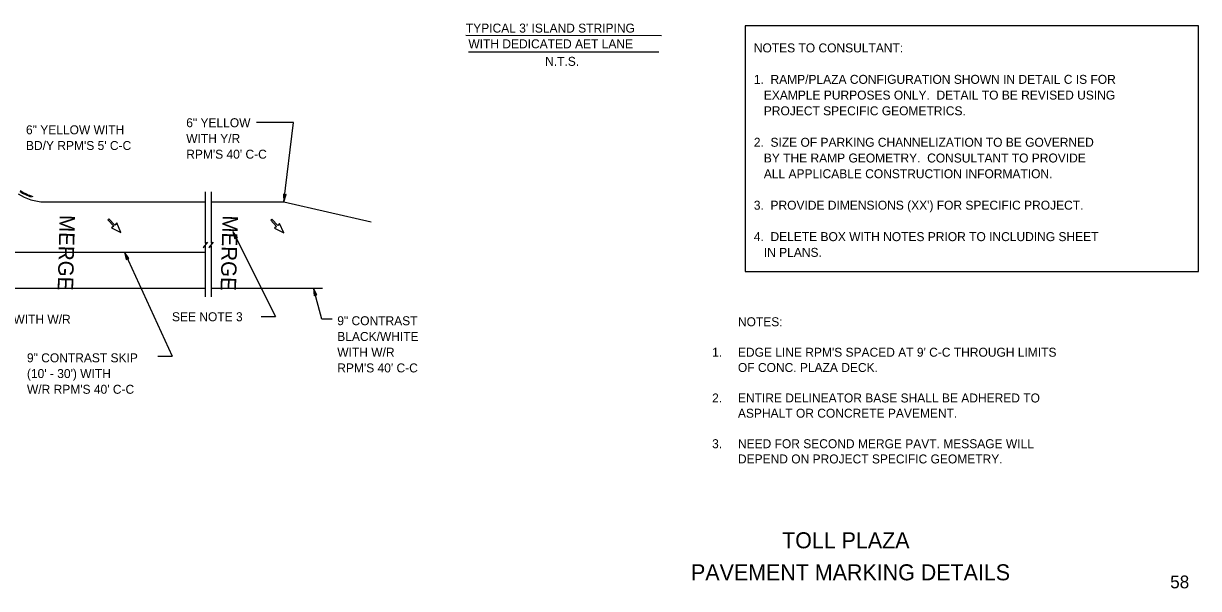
# Model space of a CAD drawing. Extents: x 583689 to 590775, y 1496016 to 1497365.
# Drawn here: x 587898 to 588815, y 1496041 to 1496482 of the extents above; entities that cross this region are included whole.
import ezdxf

# ---------------------------------------------------------------- set-up
doc = ezdxf.new("R2010")
doc.units = 0
for name, color, linetype in [('2', 7, 'Continuous'), ('20', 7, 'Continuous'), ('21', 7, 'Continuous'), ('24', 7, 'Continuous'), ('52', 7, 'Continuous'), ('6', 7, 'Continuous'), ('TextAlert', 7, 'Continuous'), ('TextMisc', 7, 'Continuous'), ('TextNotes', 7, 'Continuous'), ('TextShtNo', 7, 'Continuous')]:
    doc.layers.add(name, color=color, linetype=linetype)

msp = doc.modelspace()

# ---------------------------------------------------------------- linework, layer by layer
at = {"layer": '2'}
for p, q in [((587914.46, 1496343.13), (588039.9, 1496343.13)), ((588044.46, 1496343.13), (588101.26, 1496343.13)), ((588101.26, 1496343.13), (588169.33, 1496327.49)), ((587813.57, 1496303.79), (588039.9, 1496303.8)), ((587663.57, 1496275.75), (588039.9, 1496275.75)), ((588044.46, 1496275.75), (588131.47, 1496275.75))]:
    msp.add_line(p, q, dxfattribs=at)
for radius, end in [(37.5, 269.72056), (35.25, 253.06808), (34.5, 254.55783)]:
    msp.add_arc((587914.65, 1496380.63), radius, 236.43568, end, dxfattribs=at)
at = {"layer": '20'}
for p, q in [((587964.79, 1496329.9), (587963.89, 1496329.04)), ((587969.44, 1496325), (587964.79, 1496329.9)), ((587963.89, 1496329.04), (587968.53, 1496324.14)), ((587968.53, 1496324.14), (587966.84, 1496322.84)), ((587966.84, 1496322.84), (587974.15, 1496319.13)), ((587970.83, 1496326.63), (587969.44, 1496325)), ((587974.15, 1496319.13), (587970.83, 1496326.63)), ((588091.9, 1496329.59), (588091, 1496328.73)), ((588091, 1496328.73), (588095.64, 1496323.84)), ((588096.55, 1496324.7), (588091.9, 1496329.59)), ((588095.64, 1496323.84), (588093.95, 1496322.54)), ((588093.95, 1496322.54), (588101.26, 1496318.83)), ((588097.94, 1496326.33), (588096.55, 1496324.7)), ((588101.26, 1496318.83), (588097.94, 1496326.33))]:
    msp.add_line(p, q, dxfattribs=at)
at = {"layer": '21'}
for p, q in [((588243.28, 1496473.09), (588395.82, 1496473.08)), ((588245.24, 1496460.12), (588393.86, 1496460.11)), ((588108.87, 1496405.11), (588080.02, 1496405.16)), ((588101.26, 1496343.13), (588108.87, 1496405.11)), ((588039.9, 1496350.84), (588039.9, 1496310.79)), ((588044.46, 1496350.84), (588044.46, 1496310.79)), ((588041.64, 1496311.58), (588038.17, 1496307.48)), ((588039.9, 1496310.79), (588041.64, 1496311.58)), ((588046.19, 1496311.58), (588042.73, 1496307.48)), ((588044.46, 1496310.79), (588046.19, 1496311.58)), ((588061.46, 1496319.93), (588094.84, 1496253.66)), ((587976.89, 1496303.8), (588014.09, 1496222.75)), ((588038.17, 1496307.48), (588039.9, 1496308.74)), ((588039.9, 1496308.74), (588039.9, 1496269.01)), ((588042.73, 1496307.48), (588044.46, 1496308.74)), ((588044.46, 1496308.74), (588044.46, 1496269.01)), ((588130.93, 1496251.6), (588124.36, 1496275.75)), ((588083.63, 1496253.66), (588094.84, 1496253.66)), ((588138.85, 1496251.58), (588130.93, 1496251.6)), ((588002.88, 1496222.75), (588014.09, 1496222.75))]:
    msp.add_line(p, q, dxfattribs=at)
at = {"layer": '52'}
for p, q in [((588101.92, 1496348.45), (588100.9, 1496349.02)), ((588100.9, 1496349.02), (588101.26, 1496343.13)), ((588101.26, 1496343.13), (588103.08, 1496348.75)), ((588103.08, 1496348.75), (588101.92, 1496348.45)), ((588061.46, 1496319.93), (588063.07, 1496314.25)), ((588065.04, 1496315.24), (588061.46, 1496319.93)), ((588063.07, 1496314.25), (588063.88, 1496315.14)), ((588063.88, 1496315.14), (588065.04, 1496315.24)), ((587976.89, 1496303.8), (587978.29, 1496298.06)), ((587980.29, 1496298.97), (587976.89, 1496303.8)), ((587978.29, 1496298.06), (587979.13, 1496298.92)), ((587979.13, 1496298.92), (587980.29, 1496298.97)), ((588124.36, 1496275.75), (588124.8, 1496269.86)), ((588126.93, 1496270.44), (588124.36, 1496275.75)), ((588124.8, 1496269.86), (588125.77, 1496270.58)), ((588125.77, 1496270.58), (588126.93, 1496270.44))]:
    msp.add_line(p, q, dxfattribs=at)
at = {"layer": 'TextAlert'}
msp.add_lwpolyline([(588461.06, 1496288.7), (588814.9, 1496288.7), (588814.9, 1496480.56), (588461.06, 1496480.56)], close=True, dxfattribs=at)

# ---------------------------------------------------------------- texts
at = {"layer": '21'}
for s, p in [('6" YELLOW', (588025.07, 1496401.36)), ('6" YELLOW WITH', (587900.05, 1496395.85)), ('WITH Y/R', (588025.07, 1496389.08)), ("BD/Y RPM'S 5' C-C", (587900.05, 1496383.58)), ("RPM'S 40' C-C", (588025.07, 1496376.8)), ('SEE NOTE 3', (588013.96, 1496249.92)), ('9" CONTRAST BLACK/WHITE WITH W/R', (587758.97, 1496247.96)), ('9" CONTRAST', (588142.92, 1496246.8)), ('BLACK/WHITE', (588142.92, 1496234.52)), ('WITH W/R', (588142.92, 1496222.24)), ('9" CONTRAST SKIP', (587900.8, 1496217.86)), ("(10' - 30') WITH", (587900.8, 1496205.58)), ("RPM'S 40' C-C", (588142.92, 1496209.97)), ("W/R RPM'S 40' C-C", (587900.8, 1496193.3))]:
    msp.add_text(s, height=7, dxfattribs=at).set_placement(p)
at = {"layer": '24'}
for p in [(587926.36, 1496332.98), (588053.47, 1496332.67)]:
    msp.add_text('MERGE', height=11.999, rotation=268.44195, dxfattribs=at).set_placement(p)
at = {"layer": '6'}
for s, p in [("TYPICAL 3' ISLAND STRIPING", (588243.28, 1496475.23)), ('WITH DEDICATED AET LANE', (588245.24, 1496462.95)), ('N.T.S.', (588305.11, 1496449.28))]:
    msp.add_text(s, height=7, rotation=359.99873, dxfattribs=at).set_placement(p)
at = {"layer": 'TextAlert'}
for s, p in [('NOTES TO CONSULTANT:  ', (588467.95, 1496459.77)), ('1.  RAMP/PLAZA CONFIGURATION SHOWN IN DETAIL C IS FOR', (588467.95, 1496435.22)), ('   EXAMPLE PURPOSES ONLY.  DETAIL TO BE REVISED USING', (588467.95, 1496422.94)), ('   PROJECT SPECIFIC GEOMETRICS.', (588467.95, 1496410.66)), ('2.  SIZE OF PARKING CHANNELIZATION TO BE GOVERNED ', (588467.95, 1496386.11)), ('   BY THE RAMP GEOMETRY.  CONSULTANT TO PROVIDE ', (588467.95, 1496373.83)), ('   ALL APPLICABLE CONSTRUCTION INFORMATION.', (588467.95, 1496361.55)), ("3.  PROVIDE DIMENSIONS (XX') FOR SPECIFIC PROJECT.", (588467.95, 1496337)), ('4.  DELETE BOX WITH NOTES PRIOR TO INCLUDING SHEET', (588467.95, 1496312.45)), ('   IN PLANS.', (588467.95, 1496300.17))]:
    msp.add_text(s, height=7, dxfattribs=at).set_placement(p)
at = {"layer": 'TextMisc'}
for s, p in [('       TOLL PLAZA       ', (588457.51, 1496072.68)), ('PAVEMENT MARKING DETAILS', (588418.95, 1496047.68))]:
    msp.add_text(s, height=12.5, rotation=360, dxfattribs=at).set_placement(p)
at = {"layer": 'TextNotes'}
for s, p in [('NOTES:', (588455.54, 1496246.01)), ('1.', (588435.38, 1496222.21)), ("EDGE LINE RPM'S SPACED AT 9' C-C THROUGH LIMITS", (588455.54, 1496222.21)), ('OF CONC. PLAZA DECK.', (588455.54, 1496210.31)), ('2.  ', (588435.38, 1496186.51)), ('ENTIRE DELINEATOR BASE SHALL BE ADHERED TO', (588455.54, 1496186.51)), ('ASPHALT OR CONCRETE PAVEMENT.', (588455.54, 1496174.61)), ('3.', (588435.38, 1496150.81)), ('NEED FOR SECOND MERGE PAVT. MESSAGE WILL', (588455.54, 1496150.81)), ('DEPEND ON PROJECT SPECIFIC GEOMETRY.', (588455.54, 1496138.91))]:
    msp.add_text(s, height=7, rotation=0.00014, dxfattribs=at).set_placement(p)
at = {"layer": 'TextShtNo'}
msp.add_text('58', height=10, rotation=360, dxfattribs=at).set_placement((588792.8, 1496041.43))

doc.saveas('drawing.dxf')
